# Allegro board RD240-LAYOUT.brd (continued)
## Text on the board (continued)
User.5: 2 | 1 | 7 | 6 | 4 | 5 | 3 | C43 | C44 | R99 | C45 | C77 | R96 | IC3 | C76 | R90 | R170 | R169 | C75 | R811 | C805 | C808 | R101 | R175 | R102 | R176 | R810 | C806 | D84 | R809 | C802 | IC81 | D81 | R808 | D80 | R117 | R812 | D14 | D90 | IC12 | R831 | R827 | R819 | R823 | R828 | R816 | R820 | R824 | R67 | R59 | R49 | IC10 | R66 | R64 | R211 | R210 | C99 | R45 | C25 | C22 | R57 | R56 | R60 | R61 | R43 | R47 | R42 | R46 | IC1 | R7 | C36 | R85 | R8 | C34 | R81 | R120 | D16 | C56 | R137 | R136 | D17 | D18 | D19 | D46 | D47 | D22 | Q8 | Q25 | Q14 | D20 | D26 | D21 | D35 | D51 | D52 | D28 | Q28 | D54 | D53 | R213 | Q9 | D34 | Q10 | R20 | R212 | C27 | R18 | R19 | R76 | D56 | D55 | R22 | R214 | R23 | IC8 | C100 | Q24 | C59 | Q23 | Q22 | C92 | Q21 | R202 | R203 | Q20 | R199 | R205 | C93 | R832 | R98 | C46 | R177 | R97 | C47 | C42 | C49 | R179 | D49 | R198 | C48 | R100 | R178 | R174 | R103 | R93 | C40 | R104 | C50 | C39 | R171 | R227 | R89 | R91 | R1 | R92 | C38 | R228 | R2 | D82 | D83 | R806 | R807 | R800 | R802 | R801 | C801 | R9 | C103 | C815 | R185 | R817 | R825 | R829 | R821 | C23 | R69 | C26 | C24 | R54 | R44 | R62 | R75 | R48 | C21 | C20 | R79 | R80 | D13 | R95 | R94 | D12 | R29 | C19 | C66 | R116 | IC11 | C67 | R215 | D58 | D27 | D57 | R24 | R21 | C51 | R105 | R6 | R200 | R201 | C94 | R204 | R206 | C104 | C102
User.6: 1 | 2 | 6 | 7 | 3 | 4 | 5
